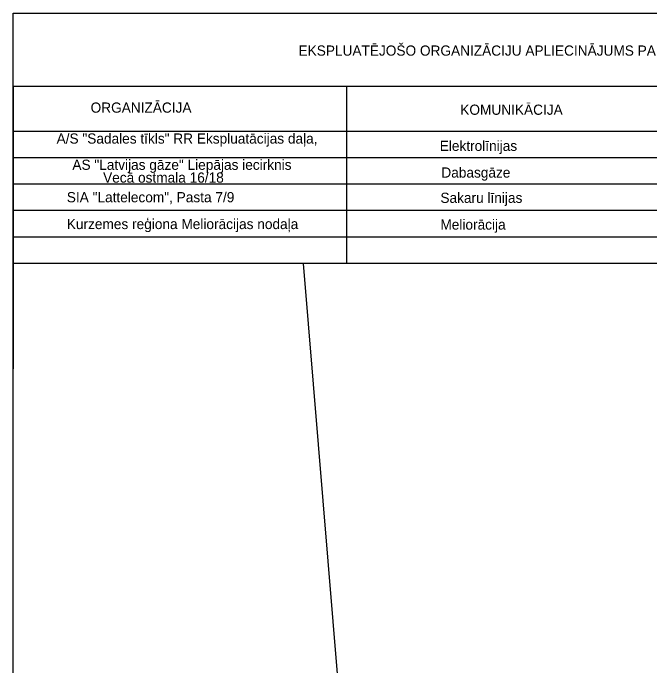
# Model space of a CAD drawing. Extents: x 321079 to 321220, y 257030 to 257220.
# Drawn here: x 321079 to 321135.2, y 257162.3 to 257219.9 of the extents above; entities that cross this region are included whole.
import ezdxf

# ---------------------------------------------------------------- set-up
doc = ezdxf.new("R2010")
doc.units = 0
doc.layers.add('RAMI_PLAN_####_TKST_#', color=7, linetype='Continuous')
doc.layers.add('ROBZ_UZMR_####_####_#', color=7, linetype='Continuous')

msp = doc.modelspace()

# ---------------------------------------------------------------- linework, layer by layer
at = {"layer": 'RAMI_PLAN_####_TKST_#'}
for p, q in [((321079.02, 257213.399), (321079.018, 257188.49)), ((321218.314, 257213.399), (321079.019, 257213.399)), ((321108.401, 257213.399), (321108.4, 257197.779)), ((321218.314, 257209.425), (321079.019, 257209.425)), ((321218.314, 257207.096), (321079.019, 257207.096)), ((321218.314, 257204.767), (321079.019, 257204.767)), ((321218.314, 257202.438), (321079.019, 257202.438)), ((321218.314, 257200.107), (321079.019, 257200.107)), ((321218.314, 257197.779), (321079.019, 257197.779))]:
    msp.add_line(p, q, dxfattribs=at)
msp.add_lwpolyline([(321079.019, 257029.866), (321079.019, 257219.866), (321218.314, 257219.866), (321218.314, 257029.866)], close=True, dxfattribs=at)
at = {"layer": 'ROBZ_UZMR_####_####_#'}
msp.add_line((321109.842, 257134.432), (321104.62, 257197.779), dxfattribs=at)

# ---------------------------------------------------------------- texts
at = {"layer": 'RAMI_PLAN_####_TKST_#'}
for s, p in [('EKSPLUATĒJOŠO ORGANIZĀCIJU APLIECINĀJUMS PAR PLĀNĀ UZRĀDĪTO APAKŠZEMES KOMUNIKĀCIJU ATBILSTĪBU ŠO ORGANIZĀCIJU ARHĪVU MATERIĀLIEM', (321104.18, 257216.106)), ('ORGANIZĀCIJA', (321085.854, 257211.076)), ('KOMUNIKĀCIJA', (321118.439, 257210.89)), (' A/S "Sadales tīkls" RR Ekspluatācijas daļa, ', (321082.522, 257208.348)), (' Elektrolīnijas', (321116.293, 257207.705)), ('AS "Latvijas gāze" Liepājas iecirknis', (321084.245, 257206.036)), ('Dabasgāze', (321116.769, 257205.349)), ('Vecā ostmala 16/18', (321086.955, 257204.903)), ('SIA "Lattelecom", Pasta 7/9', (321083.755, 257203.172)), ('Sakaru līnijas', (321116.686, 257203.122)), ('Kurzemes reģiona Meliorācijas nodaļa', (321083.755, 257200.809)), ('Meliorācija', (321116.686, 257200.759))]:
    msp.add_text(s, height=0.9, dxfattribs=at).set_placement(p)

doc.saveas('drawing.dxf')
